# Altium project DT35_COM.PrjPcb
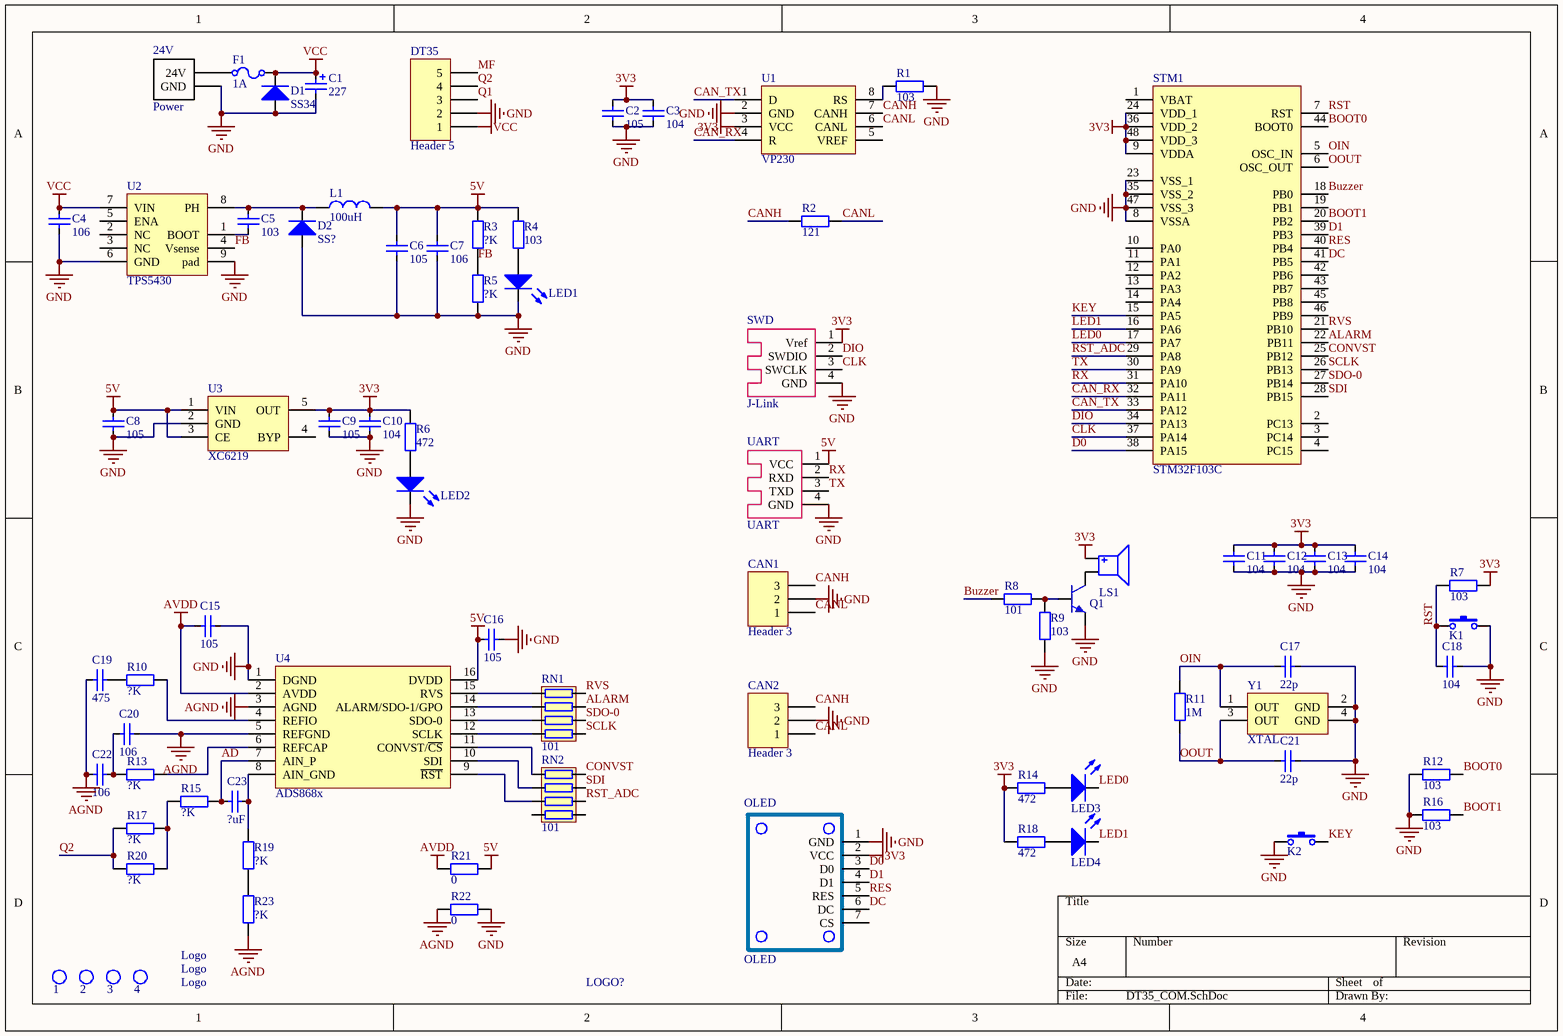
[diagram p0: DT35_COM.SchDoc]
1 sheet, 79 parts. Net scope: global (net labels, ports and power ports of the same name join across sheets).
Board file: DT35_COM.PcbDoc

## Sheet DT35_COM.SchDoc
size A4

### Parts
1  Hole  [HOLE2]  (value not drawn)
2  Hole  [HOLE2]  (value not drawn)
3  Hole  [HOLE2]  (value not drawn)
4  Hole  [HOLE2]  (value not drawn)
24V  Power  [MEM030-350-2P]
C1  value 227  [C10X10]  (hidden comment: Cap_ELEC)
C2  value 105  [C0603]  (hidden comment: Cap)
C3  value 104  [C0603]  (hidden comment: Cap)
C4  value 106  [C1210]  (hidden comment: Cap)
C5  value 103  [C0603]  (hidden comment: Cap)
C6  value 105  [C0603]  (hidden comment: Cap)
C7  value 106  [C1210]  (hidden comment: Cap)
C8  value 105  [C0603]  (hidden comment: Cap)
C9  value 105  [C0603]  (hidden comment: Cap)
C10  value 104  [C0603]  (hidden comment: Cap)
C11  value 104  [C0603]  (hidden comment: Cap)
C12  value 104  [C0603]  (hidden comment: Cap)
C13  value 104  [C0603]  (hidden comment: Cap)
C14  value 104  [C0603]  (hidden comment: Cap)
C15  value 105  [C0603]  (hidden comment: Cap)
C16  value 105  [C0603]  (hidden comment: Cap)
C17  value 22p  [C0603]  (hidden comment: Cap)
C18  value 104  [C0603]  (hidden comment: Cap)
C19  value 475  [C0603]  (hidden comment: Cap)
C20  value 106  [C0603]  (hidden comment: Cap)
C21  value 22p  [C0603]  (hidden comment: Cap)
C22  value 106  [C0603]  (hidden comment: Cap)
C23  value ?uF  [C0603]  (hidden comment: Cap)
CAN1  Header 3  [XH2.54-3]
CAN2  Header 3  [XH2.54-3]
D1  SMA: SS34  [DO-214AC]  (hidden comment: Diode)
D2  SMA: SS?  [DO-214AC]  (hidden comment: Diode)
DT35  Header 5  [XH2.54-5]
F1  value 1A  [FUSE_1206]  (hidden comment: Fuse)
K1  SW-PB  [SW_4.2x3.2]  (value not drawn)
K2  SW-PB  [SW_4.2x3.2]  (value not drawn)
L1  100uH  [L-SMD-7X7]
LED1  LED  [LED_0603_BLUE]  (value not drawn)
LED2  LED  [LED_0603_BLUE]  (value not drawn)
LED3  LED  [LED_0603_BLUE]  (value not drawn)
LED4  LED  [LED_0603_BLUE]  (value not drawn)
Logo  Logo  [Logo_f_3mm]
LOGO?  Robocon  [SWJTURobocon_2*2cm]  (value not drawn)
LS1  Buzzer  [BUZZER_4.8MM]  (value not drawn)
OLED  OLED  [OLED_0.96_SPI]
Q1  BJT_NPN  [SOT23]  (value not drawn)
R1  value 103  [R0603]  (hidden comment: Res)
R2  value 121  [R0603]  (hidden comment: Res)
R3  value ?K  [R0603]  (hidden comment: Res)
R4  value 103  [R0603]  (hidden comment: Res)
R5  value ?K  [R0603]  (hidden comment: Res)
R6  value 472  [R0603]  (hidden comment: Res)
R7  value 103  [R0603]  (hidden comment: Res)
R8  value 101  [R0603]  (hidden comment: Res)
R9  value 103  [R0603]  (hidden comment: Res)
R10  value ?K  [R0603]  (hidden comment: Res)
R11  value 1M  [R0603]  (hidden comment: Res)
R12  value 103  [R0603]  (hidden comment: Res)
R13  value ?K  [R0603]  (hidden comment: Res)
R14  value 472  [R0603]  (hidden comment: Res)
R15  value ?K  [R0603]  (hidden comment: Res)
R16  value 103  [R0603]  (hidden comment: Res)
R17  value ?K  [R0603]  (hidden comment: Res)
R18  value 472  [R0603]  (hidden comment: Res)
R19  value ?K  [R0603]  (hidden comment: Res)
R20  value ?K  [R0603]  (hidden comment: Res)
R21  value 0  [R0603]  (hidden comment: Res)
R22  value 0  [R0603]  (hidden comment: Res)
R23  value ?K  [R0603]  (hidden comment: Res)
RN1  101  [RES-Pack-1*4-0603]
RN2  101  [RES-Pack-1*4-0603]
STM1  STM32F103C  [STM32F_48]
SWD  J-Link  [4PIN-2.54 A]
U1  VP230  [SOIC-8-150mil]
U2  TPS5430  [TPS5430]
U3  XC6219  [SOT23-5]
U4  ADS868x  [TSSOP_16]
UART  UART  [4PIN-2.54 A]
Y1  XTAL  [XTAL-3225]

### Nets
3V3: C2.2 C3.2 C9.2 C10.2 C11.2 C12.2 C13.2 C14.2 LS1.1(Positive) OLED.2(VCC) R6.2 R7.2 R14.1 R18.1 STM1.9(VDDA) STM1.24(VDD_1) STM1.36(VDD_2) STM1.48(VDD_3) SWD.1(Vref) U1.3(VCC) U3.5(OUT)
5V: C6.2 C7.2 C8.2 C16.1 L1.2 R3.2 R4.2 R21.2 U3.1(VIN) U3.3(CE) U4.16(DVDD) UART.1(VCC)
AGND: C19.1 C20.2 C22.1 R22.1 R23.2 U4.3(AGND) U4.5(REFGND)
AVDD: C15.1 R21.1 U4.2(AVDD)
GND: 24V.2(GND) C1.2 C2.1 C3.1 C4.1 C6.1 C7.1 C8.1 C9.1 C10.1 C11.1 C12.1 C13.1 C14.1 C15.2 C16.2 C17.1 C18.1 C21.1 CAN1.2 CAN2.2 D1.1(A) D2.1(A) DT35.2 K1.2 K2.1 LED1.2(K) LED2.2(K) OLED.1(GND) Q1.2(E) R1.2 R5.1 R9.1 R12.1 R16.1 R22.2 STM1.8(VSSA) STM1.23(VSS_1) STM1.35(VSS_2) STM1.47(VSS_3) SWD.4(GND) U1.2(GND) U2.6(GND) U2.9(pad) U3.2(GND) U4.1(DGND) UART.4(GND) Y1.2(GND) Y1.4(GND)
VCC: C1.1 C4.2 D1.2(K) DT35.1 F1.2 U2.7(VIN)
AD: C23.1 R15.1 U4.7(AIN_P)
ALARM: RN1.7 STM1.22(PB11)
BOOT0: R12.2 STM1.44(BOOT0)
BOOT1: R16.2 STM1.20(PB2)
Buzzer: R8.1 STM1.18(PB0)
CAN_RX: STM1.32(PA11) U1.4(R)
CAN_TX: STM1.33(PA12) U1.1(D)
CANH: CAN1.3 CAN2.3 R2.1 U1.7(CANH)
CANL: CAN1.1 CAN2.1 R2.2 U1.6(CANL)
CLK: STM1.37(PA14) SWD.3(SWCLK)
CONVST: RN2.8 STM1.25(PB12)
D0: OLED.3(D0) STM1.38(PA15)
D1: OLED.4(D1) STM1.39(PB3)
DC: OLED.6(DC) STM1.41(PB5)
DIO: STM1.34(PA13) SWD.2(SWDIO)
FB: R3.1 R5.2 U2.4(Vsense)
KEY: K2.2 STM1.15(PA5)
LED0: LED3.2(K) STM1.17(PA7)
LED1: LED4.2(K) STM1.16(PA6)
MF: DT35.5
OIN: C17.2 R11.2 STM1.5(OSC_IN) Y1.1(OUT)
OOUT: C21.2 R11.1 STM1.6(OSC_OUT) Y1.3(OUT)
Q1: DT35.3
Q2: DT35.4 R17.1 R20.1
RES: OLED.5(RES) STM1.40(PB4)
RST: C18.2 K1.1 R7.1 STM1.7(RST)
RST_ADC: RN2.6 STM1.29(PA8)
RVS: RN1.8 STM1.21(PB10)
RX: STM1.31(PA10) UART.2(RXD)
SCLK: RN1.5 STM1.26(PB13)
SDI: RN2.7 STM1.28(PB15)
SDO-0: RN1.6 STM1.27(PB14)
TX: STM1.30(PA9) UART.3(TXD)
Net24V_1: 24V.1(24V) F1.1
NetC5_1: C5.1 U2.1(BOOT)
NetC5_2: C5.2 D2.2(K) L1.1 U2.8(PH)
NetC19_2: C19.2 R10.1
NetC20_1: C20.1 C22.2 R13.1
NetC23_2: C23.2 R19.2 U4.8(AIN_GND)
NetLED1_1: LED1.1(A) R4.1
NetLED2_1: LED2.1(A) R6.1
NetLED3_1: LED3.1(A) R14.2
NetLED4_1: LED4.1(A) R18.2
NetLS1_2: LS1.2(Negative) Q1.3(C)
NetQ1_1: Q1.1(B) R8.2 R9.2
NetR1_1: R1.1 U1.8(RS)
NetR10_2: R10.2 U4.4(REFIO)
NetR13_2: R13.2 U4.6(REFCAP)
NetR15_2: R15.2 R17.2 R20.2
NetR19_1: R19.1 R23.1
NetRN1_1: RN1.1 U4.15(RVS)
NetRN1_2: RN1.2 U4.14(ALARM/SDO-1/GPO)
NetRN1_3: RN1.3 U4.13(SDO-0)
NetRN1_4: RN1.4 U4.12(SCLK)
NetRN2_1: RN2.1 U4.11(CONVST/~{CS})
NetRN2_2: RN2.2 U4.10(SDI)
NetRN2_3: RN2.3 U4.9(~{RST})

Not connected (* = marked no-connect by the designer): OLED 7(CS); RN2 4 5; STM1 1(VBAT) 2(PC13) 3(PC14) 4(PC15) 10(PA0) 11(PA1) 12(PA2) 13(PA3) 14(PA4) 19(PB1) 42(PB6) 43(PB7) 45(PB8) 46(PB9); U1 5(VREF); U2 2(NC) 3(NC) 5(ENA); U3 4(BYP)

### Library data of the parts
1-4 = Hole: 定位孔
24V = Power_24V: 24V电源
C1 = Cap_ELEC: Capacitor
C2-C23 = Cap: Capacitor
CAN1 CAN2 = Header 3: Header, 3-Pin
DT35 = Header 5: Header, 5-Pin
K1 K2 = SW-PB: 轻触开关
L1 = Lnd: 电感
LOGO? = LOGO_Robocon: 队徽
OLED = OLED: 12864_0.96'OLED
Q1 = BJT_NPN: Transistor
R1-R23 = Res: Resistor
RN1 RN2 = RES-Pack-1*4-8x: 4排阻
STM1 = STM32F103C: MCU
SWD = Comm_SWD: 调试接口_SWD
U1 = VP230: CAN总线收发器
U2 = TPS5430: Power
U3 = XC6219: LDO
U4 = ADS868x: ADC
UART = Comm_UART: UART通信接口
Y1 = XTAL_4: Crystal Oscillator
